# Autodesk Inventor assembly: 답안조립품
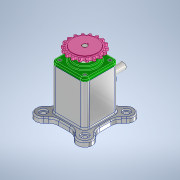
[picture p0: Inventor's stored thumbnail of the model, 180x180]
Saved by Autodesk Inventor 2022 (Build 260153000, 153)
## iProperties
Created: 2022-05
Part Number: 답안조립품
Document SubType Name: Assembly
Designer: admin
Author: admin
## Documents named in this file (11)
- C:\Users\admin\Desktop\720509V1007\답안조립품.iam
- C:\Users\admin\Desktop\720509V1007\본체.ipt
- C:\Users\admin\Desktop\720509V1007\커버.ipt
- C:\Users\admin\Desktop\720509V1007\베어링 6203.ipt
- C:\Users\admin\Desktop\720509V1007\편심축.ipt
- C:\Users\admin\Desktop\720509V1007\오일 실.ipt
- C:\Users\admin\Desktop\720509V1007\부시.ipt
- C:\Users\admin\Desktop\720509V1007\슬라이더.ipt
- C:\Users\admin\Desktop\720509V1007\키 4 x 4 x 14.ipt
- C:\Users\admin\Desktop\720509V1007\스프로킷.ipt
- C:\Users\admin\Desktop\720509V1007\볼트 M4.ipt
